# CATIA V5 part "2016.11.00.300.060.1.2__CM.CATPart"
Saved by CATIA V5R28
Part number: 2016.11.00.300.060.1.2__CM
Property "id_number": "2016.11.00.300.060.1.2"
Publications: "Absolute Axis System", "driver", "slider", "base", "cam diagram"
Bounding box of the stored display mesh (mm): x -60 to 230, y -205 to 205, z 0 to 330
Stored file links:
  N:\B2\Normteile\K\2016\11-14\030\cm\2016.11.00.300.060.1.2__CM.CATPart
  H:\CAD_Startmodelle\Tests\fill-in_PRT-SL_TEMPLATE.xlsx
  H:\CAD_Startmodelle\V5-R24\R24_TEMPLATE_PRT_FIBRO_CAM_TECNOLOGIES_INDEX.xlsx
  H:\z_Einordnen\170511__Anfrage_TK_HN\170511__CC01_TKHN.CATPart
  N:\B2\Normteile\K\2016\9xxx\2016.9024.1705.001\Entwurf_\170511__CC01_TKHN.CATPart
  N:\B2\Normteile\K\2016\9xxx\2016.9024.1707.006\Konstruktion\2016.9024.1707.006__HP__CUSTOMIZED_CAM_CM.CATPart
  N:\B2\Normteile\K\2016\9xxx\2016.9024.1707.005\Konstruktion\2016.9024.1707.005__HP__CUSTOMIZED_CAM_CM.CATPart
  N:\B2\Normteile\K\2016\9xxx\2016.9024.1707.008\Konstruktion\2016.9024.1707.008__HP__CUSTOMIZED_CAM_CM.CATPart
  N:\B2\Normteile\K\2016\9xxx\2016.9024.1707.009\Konstruktion\2016.9024.1707.009__HP__CUSTOMIZED_CAM_CM.CATPart
  N:\B2\Normteile\K\2016\9xxx\2016.9024.1707.010\Konstruktion\2016.9024.1707.010__HP__CUSTOMIZED_CAM_CM.CATPart
  N:\B2\Normteile\K\2016\9xxx\2016.9024.1708.002\Konstruktion\2016.9024.1708.002__HP__CUSTOMIZED_CAM_CM.CATPart
  N:\B2\Normteile\K\2016\9xxx\2016.9024.1802.001\Konstruktion\2016.9024.1802.001__HP__CUSTOMIZED_CAM_CM.CATPart
  N:\B2\Normteile\K\2016\9xxx\2016.9024.1802.002\Konstruktion\2016.9024.1802.002__HP__CUSTOMIZED_CAM_CM.CATPart
  N:\B2\Normteile\K\2016\9xxx\2016.9024.1811.003\Konstruktion\2016.9024.1811.003__HP__CUSTOMIZED_CAM_CM.CATPart
  N:\B2\Normteile\K\2016\9xxx\2016.9015.1811.001\Konstruktion\am\2016.9015.1811.001__AM__FCC_HV_DMC_0125-00.CATPart
  N:\B2\Normteile\K\2016\9xxx\2016.9024.1811.009\Konstruktion\2016.9024.1811.009__HP__CUSTOMIZED_CAM_CM.CATPart
  N:\B2\Normteile\K\2016\9xxx\2016.9024.1911.002\Konstruktion\am\2016.9024.1911.002__AM__CUSTOMIZED_CAM_CM.CATPart
  N:\B2\Normteile\K\2016\9xxx\2016.9024.2002.006\Konstruktion\2016.9024.2002.006__AM.CATPart
  N:\B2\Normteile\K\2016\9xxx\2016.9024.2004.001\Konstruktion\2016.9024.2004.001__AM__FCC_HV_CAEC_0260-45.CATPart
  N:\B2\Normteile\K\2016\9xxx\2016.9024.2006.002\Konstruktion\2016.9024.2006.002__AM__FCC_HV_CAEC_0260-40.CATPart
  N:\B2\Normteile\K\2016\9xxx\2016.9024.2006.005\Konstruktion\am\2016.9024.2006.005__AM__CFCC_HV_AEPC_0080-65.CATPart
  N:\B2\Normteile\K\2016\9xxx\2016.9024.2006.004\Konstruktion\am\2016.9024.2006.004__AM__CFCC_HV_AEC_0210-35.CATPart
  N:\B2\Normteile\K\2016\9xxx\2016.9026.2006.001\Konstruktion\am\2016.9026.2006.001__AM__FCC_LV_CAEC_0180-40.CATPart
  N:\B2\Normteile\K\2016\9xxx\2016.9015.2007.001\Konstruktion\am\2016.9015.2007.001__AM__FCC_HV_CDMPC_0090-00.CATPart
  N:\B2\Normteile\K\2016\9xxx\2016.9024.2005.001\Konstruktion\am\2016.9024.2005.001__AM__CFCC_HV_AEPC_1400-70.CATPart
  N:\B2\Normteile\K\2016\9xxx\2016.9024.2007.004\Konstruktion\am\2016.9024.2007.004__AM__CFCC_HV_AEC_1250-80.CATPart
  N:\B2\Normteile\K\2016\11-14\005\2016.11.00.052.040.1.02__AS__DIE_MOUNT_CAM__W52_A0_S40.CATProduct
  N:\B2\Normteile\K\2016\11-14\015\2016.11.00.150.060.1.02__AS__DIE_MOUNT_CAM__W150_A0_S60.CATProduct
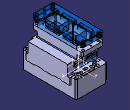
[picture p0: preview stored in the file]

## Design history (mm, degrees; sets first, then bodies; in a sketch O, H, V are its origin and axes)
Parameters
  group "process_parameters"
    modeltype = ""
    stocklist = ""
    id_number = "2016.11.00.300.060.1.2"
    id_number_rough_part = ""
    revision_index = ""
    revision_date = ""
    revision_description = ""
    category = ""
    material = ""
    manufacturing_information = ""
    standard = ""
  group "release_parameters_startmodel"
    sm_revision_index = "2016_00" {design table}
    sm_revision_date = "20.08.2016" {design table}
    sm_revision_name = "Meyer" {design table}
    sm_revision_description = "new part template FIBRO cam tecnologies" {design table}
AxisSystem1: origin (0, 0, 0), X (1, 0, 0), Y (0, 1, 0), Z (0, 0, 1)
Set1 "reference elements"
  Sketch1 "cam diagram" on ZX plane of AxisSystem1, origin (0, 0, 0), H (-1, 0, 0), V (0, 0, 1)
    line L1 (0, 0) -> (60, 0)
    line L2 (60, 0) -> (0, 60)
    point P2 (0, 60)
    line L3 (0, 60) -> (0, 0)
    length L1 = 60
    angle H L2 = 45
    horizontal: L1 H
    coincidence: P2 V
    vertical: L3 V
Body1 "finished_part" (main body)
  Body2 "rough_part"
  Add1 "rough_part": tool Body2
  Body3 "milling operations"
  Remove1 "milling operations": tool Body3
  Body4 "drilling operations"
  Remove2 "drilling operations": tool Body4
Body5 "driver"
  Solid1: solid without history
Body6 "slider"
  Solid2: solid without history
Body7 "base"
  Solid3: solid without history
Body8 "opened position"
  Body9 "slider"
    Body10 "slider"
      Solid4: linked copy from another document
    Assemble1: tool Body10
    Translate1: FirstPoint vertex [element of Sketch1 | element of Sketch1], SecondPoint vertex [element of Sketch1 | element of Sketch1], ToTransfor Assemble1
  Assemble2: tool Body9
  Body11 "driver"
    Body12 "driver"
      Solid5: linked copy from another document
    Assemble3: tool Body12
    Translate2: FirstPoint vertex [element of Sketch1 | element of Sketch1], SecondPoint vertex [element of Sketch1 | element of Sketch1], ToTransfor Assemble3
  Assemble4: tool Body11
